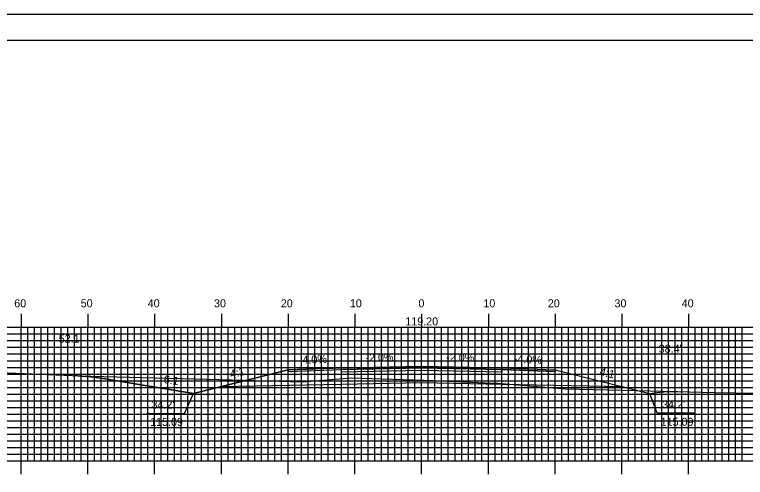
# Model space of a CAD drawing. Extents: x 1780286 to 1780629, y 442591 to 442811.
# Drawn here: x 1780390.9 to 1780500.4, y 442741.2 to 442810.5 of the extents above; entities that cross this region are included whole.
import ezdxf

# ---------------------------------------------------------------- set-up
doc = ezdxf.new("R2010")
doc.units = 0
for name, color, linetype in [('ANNOTATION', 7, 'Continuous'), ('BORDER', 7, 'Continuous'), ('D_Roadway_Centerline', 7, 'Continuous'), ('D_Roadway_Centerline_Text', 7, 'Continuous'), ('D_Roadway_Edge_Shoulder', 7, 'Continuous'), ('D_Roadway_Edge_TW', 7, 'Continuous'), ('D_Roadway_Pavement', 7, 'Continuous'), ('D_Roadway_SlopeLines', 7, 'Continuous'), ('D_Roadway_SubGrade', 7, 'Continuous'), ('D_Text_Standard', 7, 'Continuous'), ('H_V ANNOTATION', 7, 'Continuous'), ('MAJOR', 7, 'Continuous'), ('MINOR', 7, 'Continuous'), ('PLOT BOUNDARY', 7, 'Continuous'), ('S_Roadway_Centerline', 7, 'Continuous')]:
    doc.layers.add(name, color=color, linetype=linetype)

msp = doc.modelspace()

# ---------------------------------------------------------------- linework, layer by layer
at = {"layer": 'ANNOTATION'}
for points in [[(1780410.67, 442750.76), (1780416.36, 442750.76), (1780417.69, 442753.76)], [(1780492.86, 442750.78), (1780487.17, 442750.78), (1780486.04, 442753.76)]]:
    msp.add_lwpolyline(points, dxfattribs=at)
at = {"layer": 'BORDER'}
msp.add_lwpolyline([(1780302.27, 442596.67), (1780622.27, 442596.67), (1780622.27, 442806.67), (1780302.27, 442806.67)], close=True, dxfattribs=at)
at = {"layer": 'D_Roadway_Centerline'}
msp.add_lwpolyline([(1780399.74, 442756.45), (1780400.99, 442756.37), (1780402.24, 442756.26), (1780403.49, 442756.11), (1780404.74, 442755.92), (1780417.69, 442753.76), (1780421.69, 442754.76), (1780431.87, 442757.3), (1780439.87, 442757.62), (1780451.87, 442757.86), (1780463.87, 442757.62), (1780471.87, 442757.3), (1780482.04, 442754.76), (1780486.04, 442753.76), (1780487.1, 442753.91), (1780488.16, 442754.01), (1780489.21, 442754.06), (1780490.27, 442754.05)], dxfattribs=at)
at = {"layer": 'D_Roadway_Edge_Shoulder'}
for points in [[(1780439.87, 442757.62), (1780431.87, 442757.3), (1780431.87, 442757.05), (1780439.87, 442757.37)], [(1780463.87, 442757.62), (1780471.87, 442757.3), (1780471.87, 442757.05), (1780463.87, 442757.37)]]:
    msp.add_lwpolyline(points, close=True, dxfattribs=at)
at = {"layer": 'D_Roadway_Edge_TW'}
msp.add_lwpolyline([(1780439.87, 442757.37), (1780439.87, 442757.62), (1780451.87, 442757.86), (1780463.87, 442757.62), (1780463.87, 442757.37), (1780451.87, 442757.61)], close=True, dxfattribs=at)
at = {"layer": 'D_Roadway_Pavement'}
msp.add_lwpolyline([(1780439.87, 442756.96), (1780439.87, 442757.37), (1780451.87, 442757.61), (1780463.87, 442757.37), (1780463.87, 442756.96), (1780451.87, 442757.2)], close=True, dxfattribs=at)
at = {"layer": 'D_Roadway_SlopeLines'}
for points in [[(1780431.87, 442757.3), (1780417.69, 442753.76)], [(1780471.87, 442757.3), (1780486.04, 442753.76)], [(1780417.69, 442753.76), (1780404.74, 442755.92), (1780403.49, 442756.11), (1780402.24, 442756.26), (1780400.99, 442756.37), (1780399.74, 442756.45)], [(1780486.04, 442753.76), (1780487.1, 442753.91), (1780488.16, 442754.01), (1780489.21, 442754.06), (1780490.27, 442754.05)]]:
    msp.add_lwpolyline(points, dxfattribs=at)
at = {"layer": 'D_Roadway_SubGrade'}
msp.add_lwpolyline([(1780439.87, 442755.12), (1780421.69, 442754.76), (1780431.87, 442757.3), (1780431.87, 442757.05), (1780439.87, 442757.37), (1780451.87, 442757.61), (1780463.87, 442757.37), (1780471.87, 442757.05), (1780471.87, 442757.3), (1780482.04, 442754.76), (1780463.87, 442755.12), (1780451.87, 442755.36)], close=True, dxfattribs=at)
at = {"layer": 'MAJOR'}
for p, q in [((1780391.87, 442765.67), (1780391.87, 442763.67)), ((1780401.87, 442765.67), (1780401.87, 442763.67)), ((1780411.87, 442765.67), (1780411.87, 442763.67)), ((1780421.87, 442765.67), (1780421.87, 442763.67)), ((1780431.87, 442765.67), (1780431.87, 442763.67)), ((1780441.87, 442765.67), (1780441.87, 442763.67)), ((1780451.87, 442765.67), (1780451.87, 442763.67)), ((1780461.87, 442765.67), (1780461.87, 442763.67)), ((1780471.87, 442765.67), (1780471.87, 442763.67)), ((1780481.87, 442765.67), (1780481.87, 442763.67)), ((1780491.87, 442765.67), (1780491.87, 442763.67)), ((1780311.87, 442763.67), (1780591.87, 442763.67)), ((1780311.87, 442763.67), (1780591.87, 442763.67)), ((1780391.87, 442743.67), (1780391.87, 442763.67)), ((1780401.87, 442743.67), (1780401.87, 442763.67)), ((1780411.87, 442743.67), (1780411.87, 442763.67)), ((1780421.87, 442743.67), (1780421.87, 442763.67)), ((1780431.87, 442743.67), (1780431.87, 442763.67)), ((1780441.87, 442743.67), (1780441.87, 442763.67)), ((1780451.87, 442743.67), (1780451.87, 442763.67)), ((1780461.87, 442743.67), (1780461.87, 442763.67)), ((1780471.87, 442743.67), (1780471.87, 442763.67)), ((1780481.87, 442743.67), (1780481.87, 442763.67)), ((1780491.87, 442743.67), (1780491.87, 442763.67)), ((1780311.87, 442758.67), (1780591.87, 442758.67)), ((1780311.87, 442753.67), (1780591.87, 442753.67)), ((1780311.87, 442748.67), (1780591.87, 442748.67)), ((1780311.87, 442743.67), (1780591.87, 442743.67)), ((1780311.87, 442743.67), (1780591.87, 442743.67)), ((1780391.87, 442741.66), (1780391.87, 442743.67)), ((1780401.87, 442741.66), (1780401.87, 442743.67)), ((1780411.87, 442741.66), (1780411.87, 442743.67)), ((1780421.87, 442741.66), (1780421.87, 442743.67)), ((1780431.87, 442741.66), (1780431.87, 442743.67)), ((1780441.87, 442741.66), (1780441.87, 442743.67)), ((1780451.87, 442741.66), (1780451.87, 442743.67)), ((1780461.87, 442741.66), (1780461.87, 442743.67)), ((1780471.87, 442741.66), (1780471.87, 442743.67)), ((1780481.87, 442741.66), (1780481.87, 442743.67)), ((1780491.87, 442741.66), (1780491.87, 442743.67))]:
    msp.add_line(p, q, dxfattribs=at)
at = {"layer": 'MINOR'}
for p, q in [((1780392.87, 442743.67), (1780392.87, 442763.67)), ((1780393.87, 442743.67), (1780393.87, 442763.67)), ((1780394.87, 442743.67), (1780394.87, 442763.67)), ((1780395.87, 442743.67), (1780395.87, 442763.67)), ((1780396.87, 442743.67), (1780396.87, 442763.67)), ((1780397.87, 442743.67), (1780397.87, 442763.67)), ((1780398.87, 442743.67), (1780398.87, 442763.67)), ((1780399.87, 442743.67), (1780399.87, 442763.67)), ((1780400.87, 442743.67), (1780400.87, 442763.67)), ((1780402.87, 442743.67), (1780402.87, 442763.67)), ((1780403.87, 442743.67), (1780403.87, 442763.67)), ((1780404.87, 442743.67), (1780404.87, 442763.67)), ((1780405.87, 442743.67), (1780405.87, 442763.67)), ((1780406.87, 442743.67), (1780406.87, 442763.67)), ((1780407.87, 442743.67), (1780407.87, 442763.67)), ((1780408.87, 442743.67), (1780408.87, 442763.67)), ((1780409.87, 442743.67), (1780409.87, 442763.67)), ((1780410.87, 442743.67), (1780410.87, 442763.67)), ((1780412.87, 442743.67), (1780412.87, 442763.67)), ((1780413.87, 442743.67), (1780413.87, 442763.67)), ((1780414.87, 442743.67), (1780414.87, 442763.67)), ((1780415.87, 442743.67), (1780415.87, 442763.67)), ((1780416.87, 442743.67), (1780416.87, 442763.67)), ((1780417.87, 442743.67), (1780417.87, 442763.67)), ((1780418.87, 442743.67), (1780418.87, 442763.67)), ((1780419.87, 442743.67), (1780419.87, 442763.67)), ((1780420.87, 442743.67), (1780420.87, 442763.67)), ((1780422.87, 442743.67), (1780422.87, 442763.67)), ((1780423.87, 442743.67), (1780423.87, 442763.67)), ((1780424.87, 442743.67), (1780424.87, 442763.67)), ((1780425.87, 442743.67), (1780425.87, 442763.67)), ((1780426.87, 442743.67), (1780426.87, 442763.67)), ((1780427.87, 442743.67), (1780427.87, 442763.67)), ((1780428.87, 442743.67), (1780428.87, 442763.67)), ((1780429.87, 442743.67), (1780429.87, 442763.67)), ((1780430.87, 442743.67), (1780430.87, 442763.67)), ((1780432.87, 442743.67), (1780432.87, 442763.67)), ((1780433.87, 442743.67), (1780433.87, 442763.67)), ((1780434.87, 442743.67), (1780434.87, 442763.67)), ((1780435.87, 442743.67), (1780435.87, 442763.67)), ((1780436.87, 442743.67), (1780436.87, 442763.67)), ((1780437.87, 442743.67), (1780437.87, 442763.67)), ((1780438.87, 442743.67), (1780438.87, 442763.67)), ((1780439.87, 442743.67), (1780439.87, 442763.67)), ((1780440.87, 442743.67), (1780440.87, 442763.67)), ((1780442.87, 442743.67), (1780442.87, 442763.67)), ((1780443.87, 442743.67), (1780443.87, 442763.67)), ((1780444.87, 442743.67), (1780444.87, 442763.67)), ((1780445.87, 442743.67), (1780445.87, 442763.67)), ((1780446.87, 442743.67), (1780446.87, 442763.67)), ((1780447.87, 442743.67), (1780447.87, 442763.67)), ((1780448.87, 442743.67), (1780448.87, 442763.67)), ((1780449.87, 442743.67), (1780449.87, 442763.67)), ((1780450.87, 442743.67), (1780450.87, 442763.67)), ((1780452.87, 442743.67), (1780452.87, 442763.67)), ((1780453.87, 442743.67), (1780453.87, 442763.67)), ((1780454.87, 442743.67), (1780454.87, 442763.67)), ((1780455.87, 442743.67), (1780455.87, 442763.67)), ((1780456.87, 442743.67), (1780456.87, 442763.67)), ((1780457.87, 442743.67), (1780457.87, 442763.67)), ((1780458.87, 442743.67), (1780458.87, 442763.67)), ((1780459.87, 442743.67), (1780459.87, 442763.67)), ((1780460.87, 442743.67), (1780460.87, 442763.67)), ((1780462.87, 442743.67), (1780462.87, 442763.67)), ((1780463.87, 442743.67), (1780463.87, 442763.67)), ((1780464.87, 442743.67), (1780464.87, 442763.67)), ((1780465.87, 442743.67), (1780465.87, 442763.67)), ((1780466.87, 442743.67), (1780466.87, 442763.67)), ((1780467.87, 442743.67), (1780467.87, 442763.67)), ((1780468.87, 442743.67), (1780468.87, 442763.67)), ((1780469.87, 442743.67), (1780469.87, 442763.67)), ((1780470.87, 442743.67), (1780470.87, 442763.67)), ((1780472.87, 442743.67), (1780472.87, 442763.67)), ((1780473.87, 442743.67), (1780473.87, 442763.67)), ((1780474.87, 442743.67), (1780474.87, 442763.67)), ((1780475.87, 442743.67), (1780475.87, 442763.67)), ((1780476.87, 442743.67), (1780476.87, 442763.67)), ((1780477.87, 442743.67), (1780477.87, 442763.67)), ((1780478.87, 442743.67), (1780478.87, 442763.67)), ((1780479.87, 442743.67), (1780479.87, 442763.67)), ((1780480.87, 442743.67), (1780480.87, 442763.67)), ((1780482.87, 442743.67), (1780482.87, 442763.67)), ((1780483.87, 442743.67), (1780483.87, 442763.67)), ((1780484.87, 442743.67), (1780484.87, 442763.67)), ((1780485.87, 442743.67), (1780485.87, 442763.67)), ((1780486.87, 442743.67), (1780486.87, 442763.67)), ((1780487.87, 442743.67), (1780487.87, 442763.67)), ((1780488.87, 442743.67), (1780488.87, 442763.67)), ((1780489.87, 442743.67), (1780489.87, 442763.67)), ((1780490.87, 442743.67), (1780490.87, 442763.67)), ((1780492.87, 442743.67), (1780492.87, 442763.67)), ((1780493.87, 442743.67), (1780493.87, 442763.67)), ((1780494.87, 442743.67), (1780494.87, 442763.67)), ((1780495.87, 442743.67), (1780495.87, 442763.67)), ((1780496.87, 442743.67), (1780496.87, 442763.67)), ((1780497.87, 442743.67), (1780497.87, 442763.67)), ((1780498.87, 442743.67), (1780498.87, 442763.67)), ((1780499.87, 442743.67), (1780499.87, 442763.67)), ((1780311.87, 442762.67), (1780591.87, 442762.67)), ((1780311.87, 442761.67), (1780591.87, 442761.67)), ((1780311.87, 442760.67), (1780591.87, 442760.67)), ((1780311.87, 442759.67), (1780591.87, 442759.67)), ((1780311.87, 442757.67), (1780591.87, 442757.67)), ((1780311.87, 442756.67), (1780591.87, 442756.67)), ((1780311.87, 442755.67), (1780591.87, 442755.67)), ((1780311.87, 442754.67), (1780591.87, 442754.67)), ((1780311.87, 442752.67), (1780591.87, 442752.67)), ((1780311.87, 442751.67), (1780591.87, 442751.67)), ((1780311.87, 442750.67), (1780591.87, 442750.67)), ((1780311.87, 442749.67), (1780591.87, 442749.67)), ((1780311.87, 442747.67), (1780591.87, 442747.67)), ((1780311.87, 442746.67), (1780591.87, 442746.67)), ((1780311.87, 442745.67), (1780591.87, 442745.67)), ((1780311.87, 442744.67), (1780591.87, 442744.67))]:
    msp.add_line(p, q, dxfattribs=at)
at = {"layer": 'PLOT BOUNDARY'}
msp.add_lwpolyline([(1780286.08, 442590.55), (1780626.08, 442590.55), (1780626.08, 442810.55), (1780286.08, 442810.55)], close=True, dxfattribs=at)
at = {"layer": 'S_Roadway_Centerline'}
msp.add_lwpolyline([(1780311.87, 442758.55), (1780328.56, 442758.42), (1780330.47, 442758.37), (1780341.82, 442758.06), (1780352.12, 442757.29), (1780353.5, 442757.25), (1780375.41, 442757.37), (1780376.06, 442757.36), (1780376.68, 442757.38), (1780399.51, 442756.46), (1780400.54, 442756.42), (1780402.33, 442756.33), (1780421.57, 442755.84), (1780434.05, 442755.5), (1780441.33, 442756.1), (1780453.75, 442755.7), (1780461.38, 442755.33), (1780463.3, 442755.31), (1780473.35, 442754.45), (1780486.1, 442754.17), (1780495.91, 442753.89), (1780507.1, 442753.7)], dxfattribs=at)

# ---------------------------------------------------------------- texts
at = {"layer": 'ANNOTATION'}
for s, rotation, p in [('-4.0%', 2.2906, (1780433.5, 442758.17)), ('-2.0%', 1.1458, (1780443.47, 442758.5)), ('-2.0%', 358.8542, (1780455.55, 442758.59)), ('-4.0%', 357.7094, (1780465.66, 442758.35)), ('4:1', 14.0362, (1780423.32, 442756.03)), ('4:1', 345.9638, (1780478.46, 442756.52)), ('6:1', 350.5377, (1780413.17, 442755.34))]:
    msp.add_text(s, height=1.2, rotation=rotation, dxfattribs=at).set_placement(p)
for s, p in [("34.2'", (1780411.41, 442751.49)), ("34.2'", (1780487.9, 442751.51)), ('115.09', (1780411.2, 442748.89)), ('115.09', (1780487.69, 442748.91))]:
    msp.add_text(s, height=1.2, dxfattribs=at).set_placement(p)
at = {"layer": 'D_Roadway_Centerline'}
for s, p in [('C', (1780451.86, 442757.86)), ('L', (1780451.87, 442757.86))]:
    msp.add_text(s, height=0.0146, dxfattribs=at).set_placement(p)
at = {"layer": 'D_Roadway_Centerline_Text'}
msp.add_text('119.20', height=1.2, dxfattribs=at).set_placement((1780449.43, 442763.96))
at = {"layer": 'D_Text_Standard'}
for s, p in [("52.1'", (1780397.51, 442761.38)), ("38.4'", (1780487.39, 442759.86))]:
    msp.add_text(s, height=1.2, dxfattribs=at).set_placement(p)
at = {"layer": 'H_V ANNOTATION'}
for s, p in [('60', (1780390.84, 442766.67)), ('50', (1780400.8, 442766.67)), ('40', (1780410.84, 442766.67)), ('30', (1780420.77, 442766.67)), ('20', (1780430.78, 442766.67)), ('10', (1780441.12, 442766.67)), ('0', (1780451.39, 442766.67)), ('10', (1780461.12, 442766.67)), ('20', (1780470.78, 442766.67)), ('30', (1780480.77, 442766.67)), ('40', (1780490.84, 442766.67))]:
    msp.add_text(s, height=1.2, dxfattribs=at).set_placement(p)

doc.saveas('drawing.dxf')
